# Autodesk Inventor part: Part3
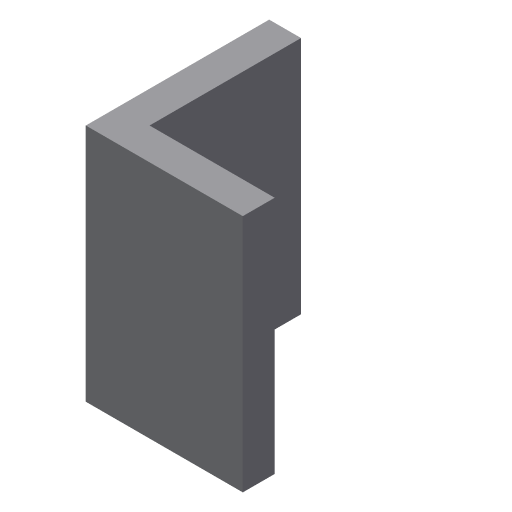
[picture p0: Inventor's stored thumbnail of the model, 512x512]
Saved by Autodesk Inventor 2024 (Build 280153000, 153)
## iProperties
Created: 2009-05
Part Number: Part3
Document SubType Name: Modeling
Designer: Sham
Density: 1 g/cm^3
Material: Generic
Appearance: Default
Author: Sham
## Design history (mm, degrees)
sketch "Sketch1"
  geometry: L1 (-20, 23)-(-20, 0); L2 (-20, 0)-(-0.309, 0); L3 (-0.309, 0)-(-0.309, 4); L4 (-0.309, 4)-(-16, 4); L5 (-16, 4)-(-16, 23); L6 (-16, 23)-(-20, 23)
  constraints: 12 end point, 5 perpendicular
extrude "Extrusion1" new body sketch "Sketch1" distance "d0" = 30; taper "d1" = 0 deg
body "Solid1"
